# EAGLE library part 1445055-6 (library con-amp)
Micro MATE-N-LOK Connectors grid 1.5 mm Source: ENG_CD_1445055_A.pdf
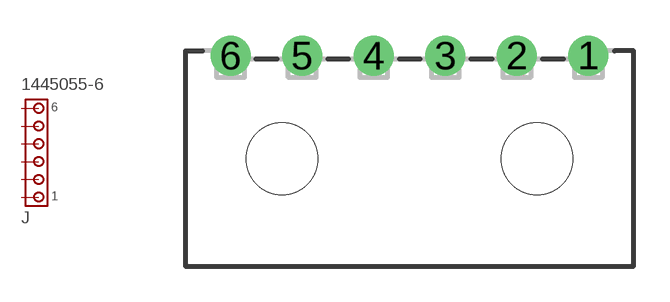
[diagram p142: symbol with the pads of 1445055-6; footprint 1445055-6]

Designator prefix J

## 1445055-6 (MPN: 2-1445055-6; OC_FARNELL: 1111122; OC_NEWARK: 98K6146)  [1445055-6]
1  1  pas
2  2  pas
3  3  pas
4  4  pas
5  5  pas
6  6  pas

## Footprint 1445055-6 (pad centres in mm)
Micro MATE-N-LOK Connectors grid 3.0 mm Source: ENG_CD_1445055_A.pdf
drill 1 pad 1.676 round: 1 7.5,4.32; 2 4.5,4.32; 3 1.5,4.32; 4 -1.5,4.32; 5 -4.5,4.32; 6 -7.5,4.32
hole 3 at -5.35,0
hole 3 at 5.35,0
